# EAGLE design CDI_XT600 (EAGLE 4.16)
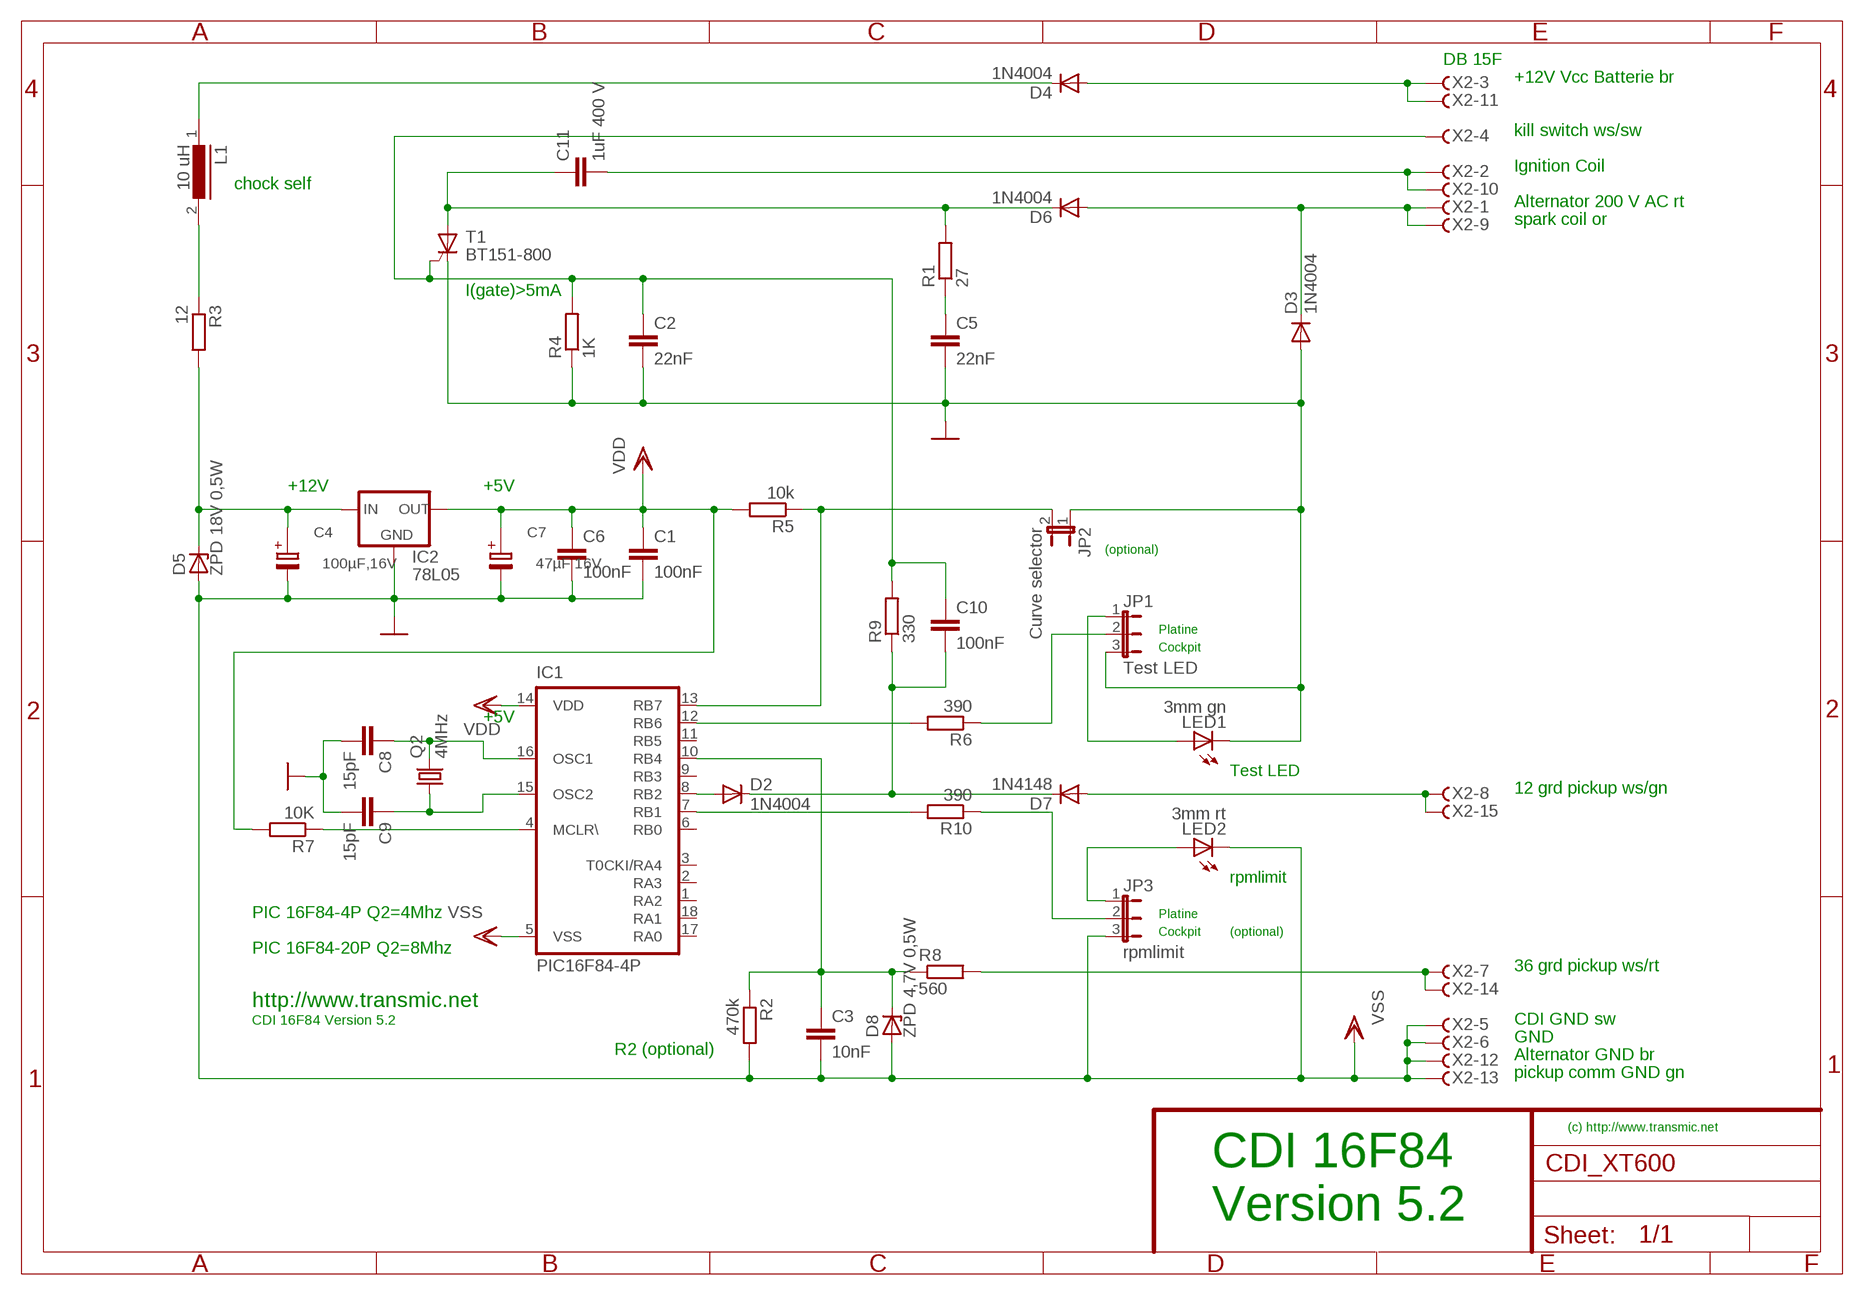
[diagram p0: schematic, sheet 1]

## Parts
C1  100nF  C-EU025-024X044  [C025-024X044]
C2  22nF  C-EU050-030X075  [C050-030X075]
C3  10nF  C-EU050-030X075  [C050-030X075]
C4  100µF,16V  E2-5@1  [E2,5-5]
C5  22nF  C-EU050-030X075  [C050-030X075]
C6  100nF  C-EU025-024X044  [C025-024X044]
C7  47µF 16V  E2-5@1  [E2,5-5]
C8  15pF  C-EU025-024X044  [C025-024X044]
C9  15pF  C-EU025-024X044  [C025-024X044]
C10  100nF  C-EU025-024X044  [C025-024X044]
C11  1uF 400 V  C22/10  [C22.5B10]
D2  1N4004  [DO41-10]
D3  1N4004  [DO41-10]
D4  1N4004  [DO41-10]
D5  ZPD 18V 0,5W  ZPD  [DO35Z10]
D6  1N4004  [DO41-10]
D7  1N4148  [DO35-10]
D8  ZPD 4,7V 0,5W  ZPD  [DO35Z10]
IC1  PIC16F84-4P  PIC16F84AP  [DIL18]
IC2  78L05  78LXX  [78LXX]
JP1  Test LED  JP2E  [JP2]
JP2  Curve selector  JP1E  [JP1]
JP3  rpmlimit  JP2E  [JP2]
L1  10 uH  LBC15  [LBC15]
LED1  3mm gn  LED3MM  [LED3MM]
LED2  3mm rt  LED3MM  [LED3MM]
Q2  4MHz  CRYTALHC18U-V  [HC18U-V]
R1  27  R-EU_0204/7  [0204/7]
R2  470k  R-EU_0204/7  [0204/7]
R3  12  R-EU_0204/7  [0204/7]
R4  1K  R-EU_0204/7  [0204/7]
R5  10k  R-EU_0204/7  [0204/7]
R6  390  R-EU_0204/7  [0204/7]
R7  10K  R-EU_0204/7  [0204/7]
R8  560  R-EU_0204/7  [0204/7]
R9  330  R-EU_0204/7  [0204/7]
R10  390  R-EU_0204/7  [0204/7]
T1  BT151-800  BT151  [TO220CL]
X2  F15HS  [F15H]

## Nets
GND: C2.2 C5.2 C8.2 C9.2 D3.A JP1.3 JP2.1 LED1.K(C) R4.1 T1.C
KILLEM: C2.1 C10.1 R4.2 R9.2 T1.G X2.4
N$1: C4.+ D5.C IC2.IN R3.2
N$2: C3.1 D8.C IC1.10(RB4) R2.1 R8.1
N$3: C8.1 IC1.16(OSC1) Q2.2
N$4: R8.2 X2.7 X2.14
N$5: D2.A IC1.8(RB2)
N$6: D7.A X2.8 X2.15
N$8: C5.1 R1.1
N$9: L1.2 R3.1
N$10: IC1.4(MCLR\) R7.1
N$11: D4.C L1.1
N$12: C9.1 IC1.15(OSC2) Q2.1
N$13: IC1.12(RB6) R6.2
N$14: C11.2 X2.2 X2.10
N$15: C11.1 D6.C R1.2 T1.A
N$16: JP1.2 R6.1
N$17: D3.C D6.A X2.1 X2.9
N$18: IC1.13(RB7) JP2.2 R5.1
N$19: JP1.1 LED1.A
N$20: D4.A X2.3 X2.11
N$21: JP3.2 R10.1
N$22: IC1.7(RB1) R10.2
N$23: JP3.1 LED2.A
N$28: C10.2 D2.C D7.C R9.1
VDD: C1.1 C6.1 C7.+ IC1.14(VDD) IC2.OUT R5.2 R7.2
VSS: C1.2 C3.2 C4.- C6.2 C7.- D5.A D8.A IC1.5(VSS) IC2.GND JP3.3 LED2.K(C) R2.2 X2.5 X2.6 X2.12 X2.13 ; supply symbol labelled GND
Unconnected: IC1.1(RA2) IC1.2(RA3) IC1.3(T0CKI/RA4) IC1.6(RB0) IC1.9(RB3) IC1.11(RB5) IC1.17(RA0) IC1.18(RA1)

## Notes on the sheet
- DB 15F
- +12V Vcc Batterie br
- kill switch ws/sw
- Ignition Coil
- chock self
- Alternator 200 V AC rt
- spark coil or
- I(gate)>5mA
- +12V | +5V
- (optional)
- Platine
- Cockpit
- +5V
- Test LED
- 12 grd pickup ws/gn
- rpmlimit
- PIC 16F84-4P Q2=4Mhz | Platine
- Cockpit | (optional)
- PIC 16F84-20P Q2=8Mhz
- 36 grd pickup ws/rt
- http://www.transmic.net
- CDI 16F84 Version 5.2 | CDI GND sw
- R2 (optional) | GND
- Alternator GND br
- pickup comm GND gn
- (c) http://www.transmic.net
- CDI 16F84
- Version 5.2

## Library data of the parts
C1-C3 C5 C6 C8-C10 = rcl:C-EU: CAPACITOR, European symbol
C4 C7 = ELKO:E2-5@1
C11 = capacitor-wima:C: CAPACITOR
D2-D4 D6 = diode:1N4004: DIODE
D5 D8 = diode:ZPD: Z DIODE
D7 = diode:1N4148: DIODE
IC1 = microchip:PIC16F8*: MICROCONTROLLER 8-Bit PIC16F8X Family - CMOS Flash/EEPROM Pin Compatible : PIC16F83, PIC16CR83, PIC16F84A, PIC16CR84 see also PIC16C*
IC2 = v-reg:78LXX: VOLTAGE REGULATOR
JP1 JP3 = jumper:JP2E: JUMPER
JP2 = jumper:JP1E: JUMPER
L1 = inductors:LBC15: INDUCTOR
LED1 LED2 = led:LED: LED
Q2 = crystal:CRYTAL: CRYSTAL
R1-R10 = rcl:R-EU_: RESISTOR, European symbol
T1 = triac:BT151: THYRISTOR
X2 = con-subd:F15?S: SUB-D

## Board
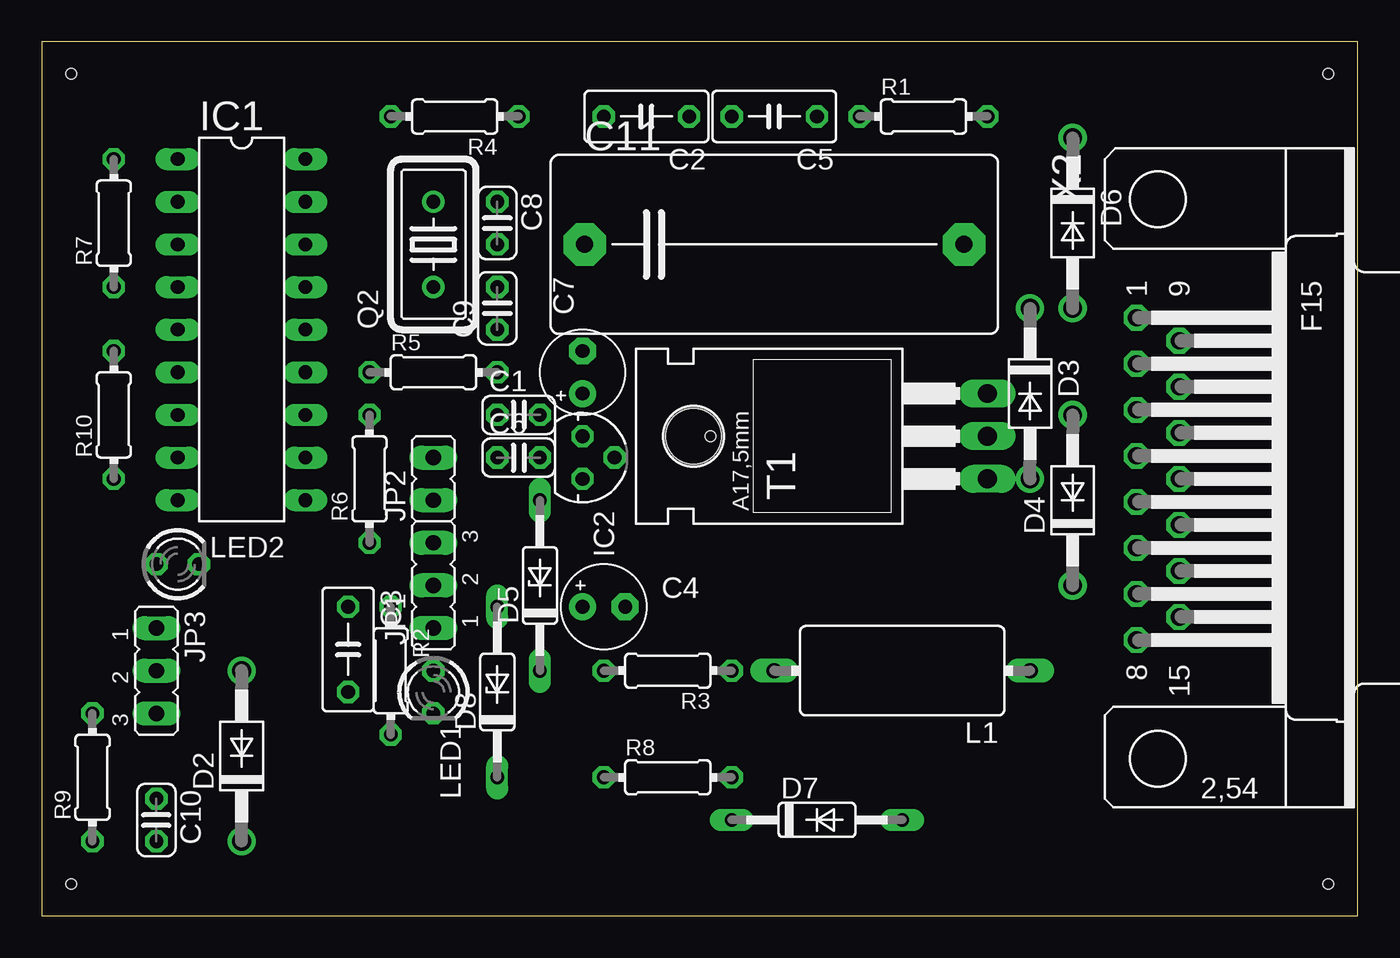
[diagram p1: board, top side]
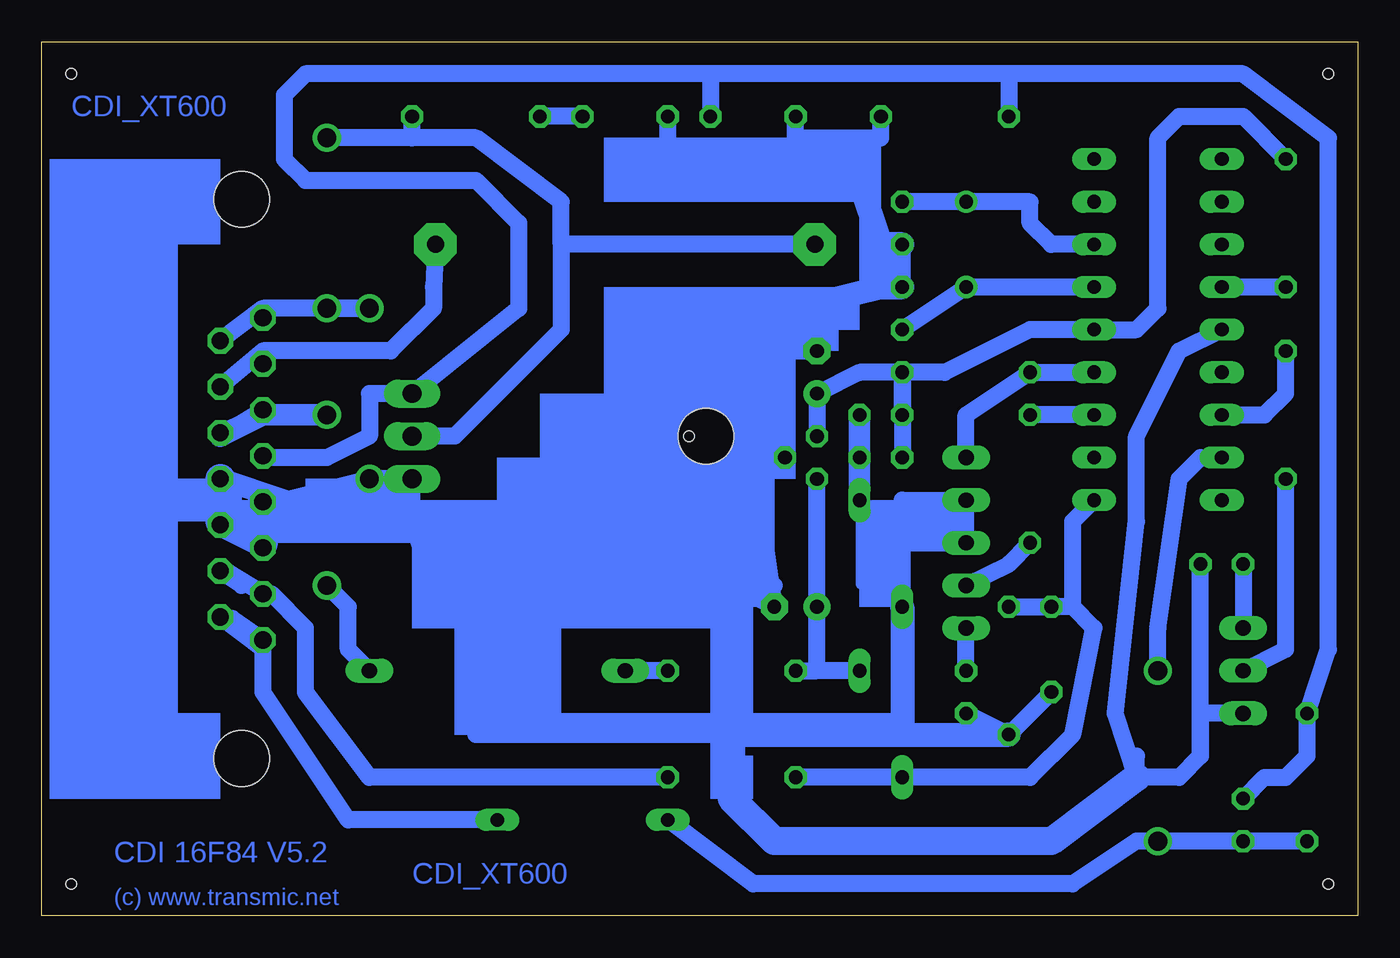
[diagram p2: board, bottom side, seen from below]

Size 78.41 x 52.06 mm. Coordinates in mm from the lower left corner, seen from the top.
Outline: 78.41,0 78.41,52.06 0,52.06 0,0 78.41,0
Copper layers (1*16): Top 0.035mm / dielectric 1.5mm / Bottom 0.035mm
Design rules "default": minimum track width 10mil, minimum drill 24mil, track to track 8mil, track to pad 8mil, pad to pad 8mil, via to via 8mil, smd to smd 8mil, copper to edge 40mil, drill to drill 8mil, minimum pad ring 10mil, minimum via ring 8mil, stop-mask expansion 4mil, vias tented up to drill 0mil, thermal gap 10mil
Holes 0.6 mm at 1.74,50.16 1.74,1.9 76.67,50.16 76.67,1.9 39.84,28.57

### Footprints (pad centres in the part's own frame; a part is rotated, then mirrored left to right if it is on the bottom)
C025-024X044 = drill 0.813 octagon: 1 -1.27,0; 2 1.27,0
C050-030X075 = drill 0.813 octagon: 1 -2.54,0; 2 2.54,0
E2,5-5 = drill 0.813 pad 1.6 round: + -1.27,0 | drill 0.813 pad 1.6 octagon: - 1.27,0
C22.5B10 = drill 1.016 pad 2.54 octagon: 1 -11.303,0; 2 11.303,0
DO41-10 = drill 1.118 round: A 5.08,0; C -5.08,0
DO35Z10 = drill 0.813 long: A 5.08,0; C -5.08,0
DO35-10 = drill 0.813 long: A 5.08,0; C -5.08,0
DIL18 = drill 0.813 long: 1 -10.16,-3.81; 2 -7.62,-3.81; 3 -5.08,-3.81; 4 -2.54,-3.81; 5 0,-3.81; 6 2.54,-3.81; 7 5.08,-3.81; 8 7.62,-3.81; 9 10.16,-3.81; 10 10.16,3.81; 11 7.62,3.81; 12 5.08,3.81; 13 2.54,3.81; 14 0,3.81; 15 -2.54,3.81; 16 -5.08,3.81; 17 -7.62,3.81; 18 -10.16,3.81
78LXX = drill 0.813 octagon: GND 0,1.905; IN 1.27,0; OUT -1.27,0
JP2 = drill 0.914 long: 1 -2.54,0; 2 0,0; 3 2.54,0
JP1 = drill 0.914 long: 1 0,-1.27; 2 0,1.27
LBC15 = drill 0.914 long: 1 -7.62,0; 2 7.62,0
LED3MM = drill 0.813 octagon: A -1.27,0; K 1.27,0
HC18U-V = drill 0.813 round: 1 -2.54,0; 2 2.54,0
0204/7 = drill 0.813 octagon: 1 -3.81,0; 2 3.81,0
TO220CL = drill 1.118 long: A 0,-6.35; C -2.54,-6.35; G 2.54,-6.35 | hole 3.302: 0,11.176
F15H = drill 1.016 octagon: 1 -9.601,-1.27; 2 -6.858,-1.27; 3 -4.115,-1.27; 4 -1.372,-1.27; 5 1.372,-1.27; 6 4.115,-1.27; 7 6.858,-1.27; 8 9.601,-1.27; 9 -8.23,1.27; 10 -5.486,1.27; 11 -2.743,1.27; 12 0,1.27; 13 2.743,1.27; 14 5.486,1.27; 15 8.23,1.27 | hole 3.302: -16.662,0; 16.662,0

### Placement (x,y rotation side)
C1  28.41,29.84 0 top
C2  36.03,47.62 180 top
C3  18.25,15.87 270 top
C4  33.49,18.41 0 top
C5  43.65,47.62 180 top
C6  28.41,27.3 0 top
C7  32.22,32.38 90 top
C8  27.14,41.27 270 top
C9  27.14,36.19 90 top
C10  6.82,5.71 270 top
C11  43.65,40 0 top
D2  11.9,9.52 90 top
D3  58.89,31.11 270 top
D4  61.43,24.76 90 top
D5  29.68,19.68 90 top
D6  61.43,41.27 270 top
D7  46.19,5.71 0 top
D8  27.14,13.33 90 top
IC1  11.9,34.92 270 top
IC2  32.22,27.3 270 top
JP1  23.33,19.68 90 top
JP2  23.33,26.03 0 top
JP3  6.82,14.6 270 top
L1  51.27,14.6 180 top
LED1  23.33,13.33 270 top
LED2  8.09,20.95 0 top
Q2  23.33,40 90 top
R1  52.54,47.62 0 top
R2  20.79,14.6 270 top
R3  37.3,14.6 180 top
R4  24.6,47.62 180 top
R5  23.33,32.38 0 top
R6  19.52,26.03 90 top
R7  4.28,41.27 90 top
R8  37.3,8.25 0 top
R9  3.01,8.25 90 top
R10  4.28,29.84 90 top
T1  50,28.57 90 top
X2  66.51,26.03 270 top

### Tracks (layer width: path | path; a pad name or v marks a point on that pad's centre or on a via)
GND
  Bottom 0.406: 27.14,22.22 27.14,24.76
  Bottom 1.016: R4.1 28.41,46.35 33.49,46.35 | 33.49,46.35 33.49,45.08 41.11,45.08 C5.2 | 33.49,46.35 C2.2 | 29.68,43.81 33.49,43.81 33.49,46.35 | C9.2 C8.2 | 27.14,24.76 JP2.1 JP1.3 27.14,22.22 27.14,18.41 | 63.97,24.76 D3.A T1.C 56.35,23.49 52.54,19.68 52.54,10.79 37.3,10.79 | 37.3,10.79 38.57,33.65 34.76,33.65 | 27.14,10.79 20.79,10.79 LED1.K | 9.36,12.06 9.36,9.52 10.63,8.25 13.17,8.25 13.17,9.52 | C9.2 C8.2 | C9.2 C8.2 | 37.3,10.79 37.3,36.19 33.49,36.19
  Bottom 1.27: 63.97,24.76 67.78,26.03
  Bottom 1.422: C8.2 28.41,40 29.68,43.81 | 33.49,36.19 28.41,37.46 C9.2 | 37.3,10.79 27.14,10.79 27.14,18.41
  Bottom 1.676: 37.3,10.79 37.3,6.98 34.76,4.44 18.25,4.44 13.17,8.25
KILLEM
  Bottom 1.016: C10.1 5.55,8.25 4.28,8.25 3.01,9.52 R9.2 1.74,15.87 1.74,46.35 6.82,50.16 20.79,50.16 | X2.4 65.24,27.3 61.43,27.3 58.89,28.57 58.89,31.11 T1.G 50,36.19 50,41.27 52.54,43.81 62.7,43.81 63.97,45.08 63.97,48.89 62.7,50.16 38.57,50.16 | 38.57,50.16 C2.1 | 20.79,50.16 38.57,50.16 | 20.79,50.16 R4.2
N$1
  Bottom 0.406: 32.22,14.6 C4.+
  Bottom 1.016: D5.C 32.22,14.6 | R3.2 32.22,14.6 | 32.22,14.6 IC2.IN
N$2
  Bottom 1.016: R8.1 D8.C 19.52,8.25 16.98,10.79 15.71,17.14 16.98,18.41 | 16.98,18.41 16.98,23.49 IC1.10 | 16.98,18.41 C3.1 R2.1
N$3
  Bottom 1.016: C8.1 Q2.2 19.52,42.54 19.52,41.27 18.25,40 IC1.16
N$4
  Bottom 1.016: R8.2 58.89,8.25 62.7,13.33 62.7,17.14 64.73,19.17 X2.7 67.27,20.44 66.51,19.68 X2.14
N$5
  Bottom 1.016: IC1.8 9.36,27.3 10.63,26.03 11.9,17.14 D2.A
N$6
  Bottom 1.016: D7.A 60.16,5.71 65.24,13.33 65.24,15.87 | 65.24,15.87 67.07,17.7 X2.8 65.24,15.87 | 65.24,15.87 X2.15
N$8
  Bottom 1.016: C5.1 R1.1
N$9
  Bottom 1.016: R3.1 L1.2
N$10
  Bottom 1.016: R7.1 IC1.4
N$11
  Bottom 1.016: L1.1 60.16,15.87 60.16,18.41 D4.C
N$12
  Bottom 1.016: IC1.15 Q2.1 C9.1
N$13
  Bottom 1.016: IC1.12 R6.2
N$14
  Bottom 1.016: 65.24,33.65 X2.10 | 65.24,33.65 X2.2 | C11.2 55.08,37.46 55.08,36.19 57.62,33.65 65.24,33.65
N$15
  Bottom 1.016: 56.35,46.35 D6.C | 47.46,40 47.46,34.92 53.81,28.57 T1.A | 47.46,40 47.46,42.54 52.54,46.35 56.35,46.35 | 56.35,46.35 R1.2 | C11.1 47.46,40
N$16
  Bottom 1.016: JP1.2 20.79,20.95 R6.1
N$17
  Bottom 1.016: D6.A D3.C 65.24,36.19 | 65.24,36.19 X2.9 | 65.24,36.19 X2.1
N$18
  Bottom 1.016: JP2.2 23.33,29.84 R5.1 IC1.13
N$19
  Bottom 1.016: LED1.A JP1.1
N$20
  Bottom 1.016: 65.24,29.84 X2.11 | 67.78,28.57 X2.3
  Bottom 1.27: D4.A 65.24,29.84 67.78,28.57
N$21
  Bottom 1.016: JP3.2 4.28,15.87 R10.1
N$22
  Bottom 1.016: R10.2 4.28,31.11 5.55,29.84 IC1.7
N$23
  Bottom 1.016: LED2.A JP3.1
N$28
  Bottom 1.016: D7.C 36.03,1.9 16.98,1.9 13.17,4.44 D2.C C10.2 R9.1
VDD
  Bottom 1.016: IC2.OUT C7.+ 29.68,32.38 R5.2 | C1.1 R5.2 | R5.2 24.6,32.38 19.52,34.92 IC1.14 13.17,34.92 11.9,36.19 11.9,46.35 10.63,47.62 6.82,47.62 | R5.2 C1.1 | C1.1 C6.1 | 6.82,47.62 R7.2 6.82,47.62
VSS
  Bottom 0.254: 67.78,23.49 X2.13
  Bottom 0.406: C1.2 C6.2 D5.A 29.68,19.68 D8.A
  Bottom 1.016: 36.03,27.3 IC2.GND 34.12,33.02 37.3,33.65 | 36.03,27.3 C4.- 37.3,19.68 | 37.3,33.65 C7.- | 36.03,27.3 37.3,33.65 | IC1.5 10.63,33.65 13.17,28.57 13.17,23.49 14.44,12.06 13.17,8.25 | JP3.3 9.36,12.06 | R2.2 C3.2 | 27.14,10.79 D8.A | 9.36,12.06 LED2.K | 9.36,12.06 9.36,9.52 10.63,8.25 13.17,8.25 | 37.3,19.68 37.3,10.79 37.3,6.98 34.76,4.44 18.25,4.44 13.17,8.25 | 34.76,19.68 37.3,19.68 | 37.3,19.68 55.08,19.68 56.35,23.49 65.24,23.49 | 65.24,22.22 X2.6
  Bottom 1.27: C6.2 C1.2 | C6.2 C1.2 | C1.2 C6.2 | C6.2 C1.2 | C1.2 C6.2 | C6.2 C1.2 | D5.A C6.2
  Bottom 1.422: 37.3,10.79 27.14,10.79 R2.2
  Bottom 1.778: X2.12 67.78,23.49 65.24,22.22 65.24,23.49 X2.5
(copper drawn outside any net)
  shapes: Bottom area x50

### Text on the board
Bottom: CDI_XT600 | CDI 16F84 V5.2 | CDI_XT600 | (c) www.transmic.net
